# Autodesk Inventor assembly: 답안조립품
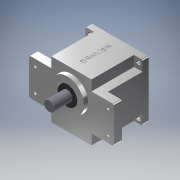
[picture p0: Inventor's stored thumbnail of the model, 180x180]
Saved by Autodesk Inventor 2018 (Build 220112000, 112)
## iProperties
Created: 2020-07
Part Number: 답안조립품
Material: 일반
Document SubType Name: Assembly
Designer: Admin
Author: Admin
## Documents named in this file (10)
- C:\Users\Admin\Desktop\700707V1006\답안조립품.iam
- C:\Users\Admin\Desktop\700707V1006\본체.ipt
- C:\Users\Admin\Desktop\700707V1006\커버.ipt
- C:\Users\Admin\Desktop\700707V1006\메인 축.ipt
- C:\Users\Admin\Desktop\700707V1006\서브 축.ipt
- C:\Users\Admin\Desktop\700707V1006\베어링 6003.ipt
- C:\Users\Admin\Desktop\700707V1006\베어링 608.ipt
- C:\Users\Admin\Desktop\700707V1006\오일 실 8 22 7.ipt
- C:\Users\Admin\Desktop\700707V1006\오일 실 17 32 8.ipt
- C:\Users\Admin\Desktop\700707V1006\볼트 M4.ipt
